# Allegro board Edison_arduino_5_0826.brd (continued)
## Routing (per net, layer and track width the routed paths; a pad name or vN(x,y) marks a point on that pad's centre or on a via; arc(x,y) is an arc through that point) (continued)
N30158362: length 3
  TOP w0.127: C42.1 98.73,32.75 R76.1 98,33 97.75,33.25 97.25,33.25 97,33.5 U3.11
N30158364: length 2.3
  TOP w0.127: U3.10 R77.1 97.23,32.75 C43.1
N30158410: length 2.4
  TOP w0.127: U3.9 96,33.5 95.75,33.25 C44.1 95.73,32.75 R78.1
N30158412: length 3.2
  TOP w0.127: R79.1 94.23,32.75 C45.1 94.25,33.25 94.5,33.5 95.25,33.5 95.5,33.75 U3.8
N30173574: length 47.5
  TOP w0.127: v1(72.39,26.04) 71.61,25.25 U34.16 ; U22.D2 102.75,38.68 v1(102.48,38.95) 102.48,38.98 103.02,39.52 104.83,39.52 R109.2
  BOTTOM w0.127: v1(102.48,38.95) 101.15,40.29 97.69,40.29 97.18,39.78 91.85,39.78 91.47,39.4 91.47,35.21 89.18,32.92 80.8,32.92 77.37,29.49 75.85,29.49 v1(72.39,26.04)
N30202561: length 3
  TOP w0.2: DS1.1 Q8.3
N30202678: length 1.8
  TOP w0.2: R86.1 37.7,39.86 DS1.2
N30202793: length 3.2
  TOP w0.2: Q9.3 49.26,28.68 49.76,29.18 DS2.1
N30202823: length 2.2
  TOP w0.2: DS2.2 48.62,29.9 R88.1
N30230113: length 1.3
  TOP w0.127: C48.2 113.59,7.62 U2.16
N30245034: length 19.5
  TOP w0.112: EU1.3 111.26,30.89 111.13,30.76 110.26,30.76 109.88,30.38 109.88,29.52 v1(109.6,29.24) ; J16.3 117.35,20.35 116.82,20.35 116.61,20.56 116.61,20.71 116.23,21.09 115.65,21.09 115.39,20.84 115.39,20.63 v1(115.11,20.35)
  BOTTOM w0.112: v1(109.6,29.24) 109.88,28.96 109.88,28.47 111.89,26.47 111.89,22.31 112.68,21.52 115.05,21.52 115.39,21.17 115.39,20.63 v1(115.11,20.35)
N30246500: length 18.7
  TOP w0.112: v1(115.91,20.35) 115.63,20.63 115.63,20.74 115.74,20.85 116.13,20.85 116.37,20.61 116.37,20.46 116.87,19.97 117.37,19.97 J16.2 ; EU1.4 111.26,30.39 111.13,30.52 110.36,30.52 110.12,30.28 110.12,29.52 v1(110.4,29.24)
  BOTTOM w0.112: v1(110.4,29.24) 110.12,28.96 110.12,28.57 112.13,26.57 112.13,22.41 112.78,21.76 115.15,21.76 115.63,21.27 115.63,20.63 v1(115.91,20.35)
N30246922: length 27.8
  TOP w0.127: 119.24,31.9 119.03,31.69 119.03,27.46 117.63,26.06 112.58,26.06 108.39,21.87 R95.2 105.82,21.86 105.82,19.97 106.2,19.59 Q10.5 ; 119.24,31.9 118.52,31.9 118,31.39 EU1.9 ; 119.24,31.9 SW1.1
N30246940: length 1.3
  TOP w0.127: R96.2 108.03,20.54 Q10.6
N30255447: length 1.5
  TOP w0.127: R97.1 117.77,32.92 SW1.C
N30255937: length 5.2
  TOP w0.127: Q11.1 116.97,36.35 117.33,36.71 R98.2 117.88,35.3 SW1.2
N30257530: length 1.7
  TOP w0.127: R100.2 27.16,49.87 Q12.6
N30257590: length 1.7
  TOP w0.127: R102.2 27.16,53.94 Q13.6
N30257808: length 2
  TOP w0.127: Q14.6 27.03,57.75 R104.2
N30258616: length 18
  TOP w0.127: R124.1 28.45,55.5 28,55.05 25.5,55.05 25.25,55.3 25.25,56.62 25.43,56.8 ; 25.43,56.8 25.17,57.05 25.17,58.19 24.54,58.83 20.47,58.83 19.84,58.19 18.96,58.19 R105.2 18.94,58.19 SW1UI5.1 ; 25.43,56.8 Q14.5
N30259742: length 12.5
  TOP w0.127: R124.2 R123.1 28.25,54.3 27.95,54.6 25.55,54.6 25.2,54.25 25.2,53.22 25.44,52.99 ; 25.44,52.99 Q13.5 ; 25.44,52.99 25.2,52.75 25.2,49.28 25.53,48.95 26.2,48.95 26.21,48.94 Q12.5
N30303973: length 25.4
  TOP w0.127: v1(97.94,28.35) 98.2,28.6 100.74,28.6 101.25,28.09 101.25,27.33 100.74,26.82 U44.2 ; v1(87.02,27.71) 87.02,27.59 88.42,26.19 88.42,22.38 88.04,22 88.04,20.35 88.17,20.22 U42.C2
  BOTTOM w0.127: v1(97.94,28.35) 96.04,28.35 95.78,28.6 87.91,28.6 v1(87.02,27.71)
N30303977: length 5.6
  TOP w0.127: v1(87.53,15.27) 87.79,15.53 U20.C1 ; U42.A1 v1(89.05,18.51)
  BOTTOM w0.127: v1(87.53,15.27) 87.78,15.27 88.55,16.03 88.55,17.93 89.05,18.44 v1(89.05,18.51)
N30305120: length 7.7
  TOP w0.127: U41.A1 106.2,36.34 v1(106.2,36.35) ; U22.C2 102.27,37.75 v1(102.26,37.75)
  BOTTOM w0.127: v1(102.26,37.75) 103.02,37.75 103.41,38.13 106.33,38.13 106.96,37.49 106.96,37.11 v1(106.2,36.35)
N30305448: length 5.5
  TOP w0.127: U40.A1 106.2,33.17 v1(106.2,33.17) ; v1(102.14,33.43) 102.21,33.5 102.75,33.5
  BOTTOM w0.127: v1(102.14,33.43) 102.64,33.43 102.9,33.68 104.67,33.68 105.18,33.17 v1(106.2,33.17)
N30330904: length 93.4
  TOP w0.3: 98.51,53.72 CR6.1 93.96,58.27 93.96,68.03 92.05,69.94 92.05,70 48.16,70 44.19,66.04 R3.2 ; CR7.1 105.65,54.47 C3.2 102.95,54.47 102.92,54.5 101.75,54.5 ; 104.81,51.82 105.03,51.61 U1.10 ; U1.13 102.98,50.35 102.68,50.66 102.68,51.8 102.67,51.81 ; 100.24,53.09 100.25,53.1 100.25,53.92 R80.2 ; U1.11 104.53,51.79 ; U1.12 104.03,51.67
N30330984: length 1.5
  TOP w0.3: C4.1 105.53,52.52 U1.9
N30331038: length 2.3
  TOP w0.3: U1.3 105.02,47.35 ; U1.1 104.02,47.46 ; U1.2 104.52,47.36
N30331073: length 2.4
  TOP w0.127: R1.2 99.12,48.98 100.46,47.65 100.46,47.47
N30331087: length 1.8
  TOP w0.127: R3.1 43.48,49.88 Q2.1
N30331321: length 15.1
  TOP w0.25: 45.43,33.96 45.43,33.62 C8.1 ; 45.43,33.96 45.42,33.97 v1(44.71,33.97) U38.12 ; 45.43,33.96 45.44,33.97 46.04,33.97 46.61,34.54 R115.2 ; U38.4 42.25,37.67 42.04,37.87 v1(41.43,37.87) 41.43,37.69 41.75,37.37 U38.5
  BOTTOM w0.25: TP84.1 v1(41.43,37.87) 42.43,36.87 43.98,36.87 44.71,36.13 v1(44.71,33.97)
N30331325: length 15
  TOP w0.127: U38.3 42.75,37.62 v1(42.8,37.68) 42.8,37.82 40.01,40.61 38.18,40.61 J13.2 ; R81.1 v1(45.43,36.59)
  BOTTOM w0.127: v1(45.43,36.59) 44.34,37.68 v1(42.8,37.68)
N30331509: length 1.4
  TOP w0.127: R4.2 41.75,33.34 U38.8
N30331521: length 2.7
  TOP w0.127: R5.1 R6.1 41.97,44.26 42.46,44.75 Q2.3
N30331562: length 7.8
  TOP w0.127: U38.1 43.75,37.86 42.62,38.99 42.62,42.41 R5.2
N30331635: length 5.7
  TOP w0.25: J2.1 42.5,32.59 42.75,32.84 U38.10
N30331680: length 8.4
  TOP w0.7: J1.1 114.28,63.53 ; J1.1 110.06,63.53 ; J1.1 112.17,61.42 ; J1.1 112.17,65.64
N30331714: length 6.2
  TOP w0.127: R1.1 99.15,49.91 R2.1 99.77,51.25 101.82,51.25 102.06,51.02 102.06,50.29 102.5,49.85 U1.14
N30332962: length 4.5
  TOP w0.127: C53.1 49.57,36.87 50.19,37.49 50.19,39.27 50.05,39.41 U45.9
N30333004: length 2.9
  TOP w0.127: R112.2 R111.1 47.27,38 47.66,38.39 U45.5
N30333010: length 6.2
  TOP w0.3: U45.1 46.12,40.91 46,40.79 46,40.41 ; U45.3 46.01,39.91 46,39.91 ; 46,40.41 46,39.91 ; 46,40.41 46,40.41 U45.2 ; 46,39.91 46,39.52 45.62,39.14 L2.1
N30351958: length 15.6
  TOP w0.127: R97.2 117.75,33.44 v1(117.09,34.1) CR9.1 ; v1(113.18,23.31) 113.18,23.31 CR8.1
  BOTTOM w0.127: v1(113.18,23.31) 113.18,25.2 117.09,29.11 v1(117.09,34.1)
N30369476: length 18.1
  TOP w0.127: DS3.2 41.69,42.4 v1(41.7,42.41) ; R114.1 53.66,40.58 v1(53.07,41.18)
  BOTTOM w0.127: v1(53.07,41.18) 53.07,42.62 50.79,44.9 47.07,44.9 46.79,45.17 45.39,45.17 45.05,44.83 42.42,44.83 41.2,43.6 41.2,42.92 v1(41.7,42.41)
N30369490: length 4.2
  TOP w0.127: U38.2 43.25,37.99 41.69,39.55 DS3.1

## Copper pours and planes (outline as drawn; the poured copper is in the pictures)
4.38V on TOP: 44.85,43.44 44.85,42.16 45.51,41.5 45.51,41.14 45.01,40.64 43.45,40.64 43.06,41.03 43.06,43.37 43.36,43.67 44.61,43.67
4.38V on BOTTOM: 42.4,39.2 43.41,38.19 44.8,38.19 45.75,37.24 45.75,32.67 46,32.41 47.4,32.41 47.78,32.79 47.78,34.19 50.83,37.24 50.83,43.21 50.19,43.84 43.44,43.84 42.4,42.8
5V on TOP: 48.41,34.57 50.57,36.73 50.57,41.3 49.81,41.3 49.81,42.19 49.05,42.19 49.05,42.95 48.8,43.21 48.29,43.21 48.03,43.46 48.03,44.48 47.5,45.01 47.5,46.48 46.48,47.5 46.48,64.9 49.91,68.33 89.41,68.33 91.34,66.4 91.34,59.34 97.54,53.14 97.54,51.69 98.25,50.98 98.25,49.36 99.47,48.13 99.47,46.74 97.54,46.74 97.54,43.36 97.69,43.21 103.78,43.21 104.42,43.84 105.56,43.84 105.56,42.19 105.31,41.94 88.31,41.94 88.2,42.05 88.2,44.51 85.98,46.74 84.11,46.74 83.56,47.29 83.56,49.71 84.02,50.18 88.5,50.18 91.33,47.35 93.75,47.35 94,47.6 94,49.85 93.7,50.15 91.6,50.15 88.6,53.15 86.39,53.15 86.39,54.12 84.23,56.28 81.64,56.28 80.9,57.02 80.9,61.49 81.2,61.8 82.37,61.8 82.83,62.26 82.83,63.12 52.58,63.12 49.4,59.94 49.4,51.3 50.91,49.78 50.91,43.95 52.73,42.14 52.73,33.43 52.96,33.27 54.86,33.27 55.24,32.89 55.24,31.24 54.99,30.99 50.22,30.99 48.41,32.79
5V on TOP: 91.21,38.64 88.93,38.64 88.42,39.14 88.42,40.67 90.45,40.67 91.21,39.91
5V on BOTTOM: 87.7,45.55 87.7,39.48 88.67,38.51 90.58,38.51 91.09,39.02 91.09,40.16 90.7,40.54 90.7,44.35 89.05,46 88.15,46
5V on BOTTOM: 48.16,34.06 48.16,33.3 48.8,32.67 49.68,32.67 50.45,33.43 50.45,34.06 50.19,34.32 48.41,34.32
5V on BOTTOM: 103.84,43.67 103.84,41.19 104.7,40.33 108.91,40.33 111.39,37.85 111.39,37.07 111.12,36.8 111.12,33.31 111.54,32.89 112.64,32.89 112.93,33.18 112.93,38.1 107.01,44.02 104.19,44.02
GND on TOP (solid shape): 101.18,49.77 101.46,49.49 103.35,49.49 103.42,49.42 103.42,49.19 102.95,49.19 102.95,49.01 103.42,49.01 103.42,48.82 103.35,48.75 102.98,48.75 102.54,48.31 100.66,48.31 100.4,48.57 100.4,50.29 100.56,50.45 101.18,50.45
GND on TOP: 24.16,57.43 22.89,57.43 22.63,57.18 21.49,57.18 21.36,57.3 21.36,58.19 21.49,58.32 24.16,58.32 24.28,58.19 24.28,57.56
GND on TOP: 15.53,11.54 15.53,10.88 16.56,9.85 16.93,9.85 17.13,10.04 17.13,10.44 17.41,10.73 17.41,11.43 17.17,11.67 15.66,11.67
GND on TOP: 45.57,42.97 45.73,42.97 46.56,42.15 47.83,42.15 47.99,42.31 47.99,42.61 47.25,43.35 47.25,44.88 46.14,45.98 45.38,45.98 45.17,45.77 45.17,44.17 45.57,43.77
GND on TOP: 24.16,49.56 22.89,49.56 22.63,49.3 21.49,49.3 21.36,49.43 21.36,50.32 21.49,50.45 24.16,50.45 24.28,50.32 24.28,49.68
GND on TOP: 19.2,11.61 19.43,11.61 19.43,10.69 19.46,10.67 19.58,10.67 19.61,10.69 19.61,11.61 19.81,11.61 19.81,10.69 19.84,10.67 19.99,10.67 20.02,10.69 20.02,11.61 20.22,11.61 20.22,10.69 20.24,10.67 20.4,10.67 20.42,10.69 20.42,11.61 20.62,11.61 20.62,10.08 20.5,9.96 20.09,9.96 19.66,9.53 19.66,6.76 19.28,6.38 16.56,6.38 16.03,6.91 16.03,7.77 16.74,8.48 17.09,8.48 19.2,10.59
GND on TOP: 102.62,63.63 102.62,59.18 104.14,57.66 107.82,57.66 108.74,58.57 108.74,64.67 103.66,64.67
GND on TOP: 24.16,53.62 22.89,53.62 22.63,53.37 21.49,53.37 21.36,53.49 21.36,54.38 21.49,54.51 24.16,54.51 24.28,54.38 24.28,53.75
GND on BOTTOM: 101.09,63.75 101.09,56.77 102.62,55.25 106.3,55.25 109.09,58.04 109.09,65.28 108.84,65.53 102.87,65.53
GND on GND: 121.33,0.89 0.93,0.89 0.93,71.08 121.33,71.08 ; 1 cut-out
GND on PWR_GND: 121.33,0.89 0.93,0.89 0.93,71.08 121.33,71.08 ; 1 cut-out
VBUS on TOP: 16.28,21.11 16.28,20.09 19.2,17.17 20.22,17.17 20.6,16.79 21.24,16.79 21.36,16.92 21.36,17.93 17.93,21.36 16.54,21.36
VBUS on TOP: 102.01,19.59 102.01,16.66 103.79,14.89 115.22,14.89 115.6,15.27 115.6,16.79 114.71,17.68 103.66,17.68 103.53,17.81 103.53,19.84 102.26,19.84
VBUS on PWR_GND: 116.2,37.77 116.2,16.89 116.46,16.64 121.28,16.64 121.28,0.89 15.02,0.89 15.01,20.14 16.08,21.21 17.5,21.21 18.35,20.36 18.35,3.17 18.73,2.79 107.44,2.79 113.44,8.79 113.44,22.38 114.33,23.27 114.33,34.83 107.72,41.43 107.72,41.94 108.1,42.32 111.66,42.32
VBUS_IN on TOP: 108.5,20.26 108.5,19.87 108.28,19.65 107.92,19.65 107.61,19.35 107.61,18.99 107.49,18.88 106.77,18.88 106.66,18.77 106.66,18.44 106.73,18.38 116.56,18.38 116.67,18.49 116.67,19.28 116.45,19.5 111.43,19.5 110.61,20.33 108.57,20.33
VBUS_OUT on PWR_GND: 111.53,44.86 106.2,44.86 105.82,44.48 105.82,40.41 111.64,34.59 111.64,24.48 105.6,18.44 103.79,18.44 97.31,11.97 42.83,11.97 37.75,17.05 37.75,26.82 36.48,28.09 25.94,28.09 25.55,28.48 25.55,37.11 24.79,37.87 23.9,37.87 23.14,37.11 23.14,28.35 25.81,25.68 34.44,25.68 35.46,24.67 35.46,16.66 41.3,10.82 41.3,5.74 42.19,4.85 95.53,4.85 114.07,23.4 114.07,34.7 107.34,41.43 107.34,42.32 107.72,42.7 111.53,42.7
VIN on TOP (solid shape): 100.08,59.82 100.08,56.39 98.04,56.39 98.04,57.44 97.35,58.13 95.81,58.13 95.52,58.42 95.52,61.4 95.71,61.59 98.3,61.59
VIN on TOP: 95.71,61.59 98.3,61.59 100.08,59.82 100.08,56.39 98.04,56.39 98.04,57.44 97.35,58.13 95.81,58.13 95.52,58.42 95.52,61.4
VIN on PWR_GND: 73.03,61.59 73.03,57.28 73.66,56.64 96.52,56.64 96.52,61.59
(no net) on TOP: 100.66,48.31 102.54,48.31 102.98,48.75 103.35,48.75 103.42,48.82 103.42,49.42 103.35,49.49 101.46,49.49 101.18,49.77 101.18,50.45 100.56,50.45 100.4,50.29 100.4,48.57
(no net) on TOP: 102.21,46.06 102.5,45.77 102.5,44.66 101.34,44.66 100.27,43.59 98.07,43.59 97.94,43.72 97.94,44.35 99.21,44.35 100.25,45.38 100.25,47.39 100.52,47.67 101.36,47.67 102.21,46.82
(no net) on TOP: 98.2,53.84 98.2,52.07 98.47,51.8 102.87,51.8 103.02,51.64 104.91,51.64 105.08,51.82 105.08,51.9 104.78,52.21 104.78,54.13 105.85,54.13 105.92,54.2 105.92,54.78 105.82,54.89 103.79,54.89 103.61,54.71 103.61,54.11 103.5,54 102.76,54 102.62,54.14 102.62,54.36 102.18,54.8 101.55,54.8 101.25,54.5 101.25,53.55 101,53.3 99.68,53.3 98.99,53.98 98.34,53.98
(no net) on TOP: 105.2,48.35 104.89,48.35 104.89,47.69 104.87,47.67 104.71,47.67 104.69,47.69 104.69,48.35 104.38,48.35 104.38,47.69 104.36,47.67 104.21,47.67 104.18,47.69 104.18,48.35 103.88,48.35 103.88,46.8 103.04,45.97 103.04,44.67 105.2,44.67
(no net) on TOP: 95.71,61.59 98.3,61.59 100.08,59.82 100.08,56.39 98.04,56.39 98.04,57.44 97.35,58.13 95.81,58.13 95.52,58.42 95.52,61.4
V_1P80 on PWR_GND: 12.73,64.54 70.33,64.54 72.64,62.23 72.64,57.15 73.53,56.26 98.55,56.26 99.06,55.75 99.06,46.48 103.28,42.26 103.28,40.16 105.69,40.16 111.37,34.48 111.37,24.62 105.58,18.82 103.53,18.82 97.16,12.45 42.8,12.45 38.1,17.15 38.1,26.92 36.58,28.45 26.29,28.45 26.04,28.7 26.04,37.08 24.64,38.48 17.78,38.48 17.14,39.12 17.14,41.02 11.68,41.02 10.92,41.78 10.92,62.74 ; 1 cut-out
V_1P80_IO on TOP: 21.36,52.99 21.49,53.11 23.01,53.11 23.14,53.24 24.16,53.24 24.28,53.11 24.28,51.72 24.16,51.59 21.49,51.59 21.36,51.72
V_1P80_IO on BOTTOM: 23.39,52.61 23.39,51.34 22.76,50.7 19.84,50.7 18.95,51.59 18.95,61.11 22.51,64.67 47.14,64.67 50.32,61.5 54.64,61.5 55.91,60.23 55.91,59.34 56.41,58.83 62,58.83 64.42,56.42 64.42,50.57 64.54,50.45 65.3,50.45 65.56,50.19 65.56,49.56 65.05,49.05 62,49.05 58.32,52.73 58.32,54.89 54,59.21 43.59,59.21 40.41,62.38 22.63,62.38 20.86,60.61 20.86,55.15
V_1P80_IO on BOTTOM: 66.19,28.09 66.19,27.59 67.46,26.32 69.11,26.32 69.62,25.81 70.64,25.81 70.77,25.94 70.77,26.7 70.39,27.08 69.11,27.08 67.97,28.22 66.32,28.22
V_1P80_IO on PWR_GND: 70.89,28.6 70.89,25.94 70.51,25.55 58.7,25.55 54.89,29.36 51.21,29.36 50.57,30 50.57,37.75 47.14,41.18 22.76,41.18 18.95,44.98 18.95,50.95 21.11,53.11 23.14,53.11 23.65,52.61 23.65,50.06 22.89,49.3 20.98,49.3 20.35,48.67 20.35,46.64 22.89,44.1 49.3,44.1 56.67,36.73 56.67,30.51 58.57,28.6
V_3P30 on BOTTOM: 12.07,64.01 19.18,71.12 96.31,71.12 100.08,67.35 100.08,55.93 101.78,54.23 113.28,54.23 116.99,50.52 116.99,32.16 116.61,31.78 115.47,31.78 113.31,33.94 113.31,38.25 106.88,44.69 95.83,44.69 93.78,46.74 84.64,46.74 79.22,52.15 79.22,53.37 75.45,57.14 75.45,62.55 70.81,67.18 22.35,67.18 21.97,66.8 21.97,65.91 18.41,62.36 18.41,38.61 17.91,38.1 12.57,38.1 12.07,38.61
V_SHIELD on TOP: 79.41,49.06 79.41,46.5 77.63,46.5 76.63,47.5 75.03,47.5 74.93,47.39 74.93,46.38 79.97,41.34 80.95,41.34 81.1,41.49 81.1,43.01 80.85,43.26 80.38,43.26 80.22,43.41 80.22,44.02 80.63,44.43 82.18,44.43 82.42,44.66 82.42,49.13 83.74,50.46 85.72,50.46 85.72,50.45 88.7,50.45 91.5,47.65 93.5,47.65 93.6,47.75 93.6,49.7 93.45,49.85 91.4,49.85 88.45,52.8 85.75,52.8 85.75,52.81 83.16,52.81
V_SHIELD on TOP: 54.46,40.2 54.46,39.64 55.68,39.64 57.77,37.55 57.77,34.19 58.63,33.33 60.74,33.33 61.03,33.62 61.03,35.72 55.7,41.04 55.05,41.04 54.93,40.93 54.93,40.93 54.93,40.28 54.93,40.27 54.86,40.2
V_SHIELD on BOTTOM: 88.95,60.19 88.95,55.91 85.04,52 84.7,52 84.29,51.59 84.29,51.05 84.77,50.56 85.46,50.56 90.68,55.78 90.68,60.27 90.16,60.79 89.54,60.79
V_SHIELD on BOTTOM: 75.31,47.88 79.63,47.88 82.42,45.09 82.42,36.45 77.47,31.5 74.8,31.5 74.55,31.75 74.55,32.39 76.2,34.04 76.2,43.94 74.96,45.19 74.96,47.53
V_SHIELD on GND: 62.87,40.77 74.28,40.77 74.84,41.33 77.92,41.33 78.23,41.02 78.23,38.86 77.58,38.21 75.54,38.21 74.89,38.86 62.87,38.86
V_SHIELD on PWR_GND: 64.29,40.79 64.29,40.54 64.03,40.29 61.75,40.29 59.97,42.06 59.97,53.49 59.21,54.26 56.54,54.26 56.16,53.88 56.16,48.41 55.15,47.4 28.6,47.4 27.71,48.29 27.71,49.56 27.97,49.81 46,49.81 50.45,54.26 50.45,55.65 52.86,58.07 56.54,58.07 61.37,53.24 61.37,42.19 62.51,42.19 63.4,41.3 63.78,41.3
V_SHIELD on PWR_GND: 59.94,36.45 79.3,36.45 85.35,30.4 81.29,30.4 79.28,32.41 59.59,32.41 59.59,36.09
V_SHIELD_SW on PWR_GND: outline of 121 points within 56.77,16.76 92.48,46.99
V_SHLD_IO on TOP: 21.36,48.92 21.49,49.05 22.89,49.05 23.01,49.18 24.16,49.18 24.28,49.05 24.28,47.65 24.16,47.53 21.49,47.53 21.36,47.65
V_SHLD_IO on PWR_GND: 20.6,48.41 20.6,46.76 23.01,44.35 49.43,44.35 57.05,36.73 57.05,30.63 58.83,28.86 78.77,28.86 80.8,26.82 82.58,26.82 82.6,26.85 85,26.85 85.35,27.2 85.35,29.5 85.04,29.82 81.62,29.82 79.28,32.16 59.34,32.16 59.34,38.13 56.16,41.3 56.16,46.64 55.65,47.14 25.17,47.14 23.27,49.05 21.24,49.05
V_SYS on BOTTOM: 21.36,45.11 23.9,47.65 23.9,54.38 23.27,55.02 21.87,55.02 21.36,55.53 21.36,60.61 22.35,61.59 34.29,61.59 38.23,57.66 38.23,51.82 37.72,51.31 31.75,51.31 31.12,50.67 31.12,42.09 32.79,40.41 35.97,40.41 38.63,37.75 38.63,34.7 40.03,33.3 44.86,33.3 46,32.16 47.14,32.16 47.27,32.03 47.27,31.27 46.48,30.48 31.62,30.48 30.99,31.12 21.36,31.12
V_SYSTEM on TOP: 23.05,56.96 23.14,57.05 24.16,57.05 24.28,56.92 24.28,55.53 24.16,55.4 21.5,55.4 20.3,55.4 19.85,54.95 19.85,48.45 10.65,39.25 10.65,38.45 10.5,38.3 6.4,38.3 6.1,38.6 6.1,40.45 6.48,40.83 9.03,40.83 17.7,49.5 17.7,55.2 19.46,56.96
N30057609 on TOP: 94.59,37.36 91.74,37.36 91.74,38.99 94.59,38.99
N30057609 on BOTTOM: 92.46,39.24 97.16,39.24 99.82,36.58 99.82,35.05 99.44,34.67 93.98,34.67 92.2,36.45 92.2,38.99
N30126876 on TOP: 18.62,14.99 15.36,14.99 15.15,15.19 12.75,15.19 10.79,17.15 10.79,34.29 10.03,35.05 6.6,35.05 6.1,35.56 6.1,37.97 6.22,38.1 12.19,38.1 12.32,37.97 12.32,20.83 17.6,15.54 18.34,15.54 18.62,15.27
N30126894 on TOP: 19.43,14 19.2,14 19.2,14.91 19.18,14.94 19.05,14.94 19.02,14.91 19.02,14 18.82,14 18.82,15.34 18.41,15.75 17.78,15.75 12.57,20.96 12.57,37.97 12.7,38.1 16.76,38.1 17.14,37.72 17.14,36.07 15.88,34.8 15.88,20.07 18.67,17.27 18.67,16.41 19.43,15.65
N30126899 on BOTTOM: 20.19,15.49 19.44,15.49 18.56,16.38 18.56,16.91 18.79,17.14 19.81,17.14 20.57,17.91 20.57,20.7 20.45,20.83 19.68,20.83 19.56,20.7 19.56,19.81 19.18,19.43 18.52,19.43 17.58,18.49 17.58,14.74 18.1,14.22 20.19,14.22 20.45,14.48 20.45,15.24
N30126899 on PWR_GND: 21.62,20.35 21.34,20.07 20.19,20.07 19.94,20.32 19.94,31.04 18.57,32.41 18.57,37.62 19.05,38.1 21.01,38.1 21.62,37.49
N30330904 on TOP (solid shape): 105.92,54.78 105.92,54.2 105.85,54.13 104.78,54.13 104.78,52.21 105.08,51.9 105.08,51.82 104.91,51.64 103.02,51.64 102.87,51.8 98.47,51.8 98.2,52.07 98.2,53.84 98.34,53.98 98.99,53.98 99.68,53.3 101,53.3 101.25,53.55 101.25,54.5 101.55,54.8 102.18,54.8 102.62,54.36 102.62,54.14 102.76,54 103.5,54 103.61,54.11 103.61,54.71 103.79,54.89 105.82,54.89
N30331038 on TOP (solid shape): 104.18,48.13 104.18,47.69 104.21,47.67 104.36,47.67 104.38,47.69 104.38,48.35 104.68,48.35 104.68,47.77 104.69,47.77 104.69,47.69 104.71,47.67 104.87,47.67 104.89,47.69 104.89,48.35 105.18,48.35 105.18,47.77 105.2,47.77 105.2,44.67 103.04,44.67 103.04,45.97 103.88,46.8 103.88,48.35 104.18,48.35
N30331073 on TOP (solid shape): 100.63,47.67 101.36,47.67 102.21,46.82 102.21,46.06 102.5,45.77 102.5,44.66 101.34,44.66 100.27,43.59 98.07,43.59 97.94,43.72 97.94,44.35 99.21,44.35 100.25,45.38 100.25,47.39 100.52,47.67 100.63,47.67
N30331680 on TOP: 115.7,59.56 109.5,53.37 108.74,53.37 108.33,53.78 108.33,56.52 109.5,57.69 109.5,65.31 110.14,65.94 113.82,65.94 115.7,64.06

Small or netless copper shapes (teardrops, artwork), in the pictures only: 3 on TOP

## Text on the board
BOTTOM: 4 | H40482-005
User.Comments: UNLESS OTHERWISE SPECIFIED: | 1. DIMENSIONS ARE IN INCHES | 2. BREAK ALL SHARP EDGES | 3. DO NOT SCALE DRAWING | 4. TOLERANCES | ANGLES +/- | DRN BY | CHK BY | ENGR | APVD | SIGNATURE | DATE | SCALE | TITLE | SIZE | DCLC | CLASS CODE | DOCUMENT NUMBER | SHEET | OF | REV
TOP: 1
Ref Des/Silkscreen Top: ANALOG IN | DIGITAL(PWM~) | RM | FW | RESET | PWR | SHLD RST | - | POWER | BATT | + | PWM | RX | 0 | A5 | TX | 1 | A4 | 2 | A3 | ~3 | A2 | 4 | A1 | ~5 | A0 | ~6 | 7 | VIN | GND | 8 | ~9 | 5V | ~10 | 3.3V | ~11 | 12 | IOREF | 13 | AREF | SDA | SCL
GND: 2
PWR_GND: 3
DIMENSION: -A- | -B-
PAGE_OUTLINE: THIS DRAWING CONTAINS INFORMATION | WHICH IS THE PROPRIETARY PROPERTY | OF INTEL CORPORATION. THIS DRAWING | IS RECEIVED IN CONFIDENCE AND ITS | CONTENTS MAY NOT BE DISCLOSED WITH- | OUT THE PRIOR WRITTEN CONSENT OF | INTEL CORPORATION. | D | C | B | A | 8 | 7 | 6 | 5 | 4 | 3 | 2 | 1
DISPLAY_TOP: PROCESS FLOW | WAVE & SMT
User.6: 0 | # | A | B | 1 | 2 | 3 | 4
User.7: K | L | M | 4 | 3 | 2 | 1 | 0
User.24: DETAILS "A" | 4 PLACES
User.31: SHEET | TITLE | SCALE 1:1 | LAYER | OF | DOCUMENT NUMBER | REV | H40482-005 | 01 | INTEL | MASTER | EDISON ARDUINO | 08/11/14
User.32: 4 | DEV,PB,
User.33: LAYER 4 (SECONDARY SIDE) | 4
User.34: LAYER 3 (PWR/GND PLANE) | 3
User.35: LAYER 2 (GND PLANE) | 2
User.36: LAYER 4 (SIGNAL/POWER) | 4
User.37: LAYER 5 (GND PLANE) | 5
User.38: LAYER 1 (PRIMARY SIDE) | 1
User.39: SECONDARY SIDE
User.40: jeirvin | 04/10/14 | W.GILLMER | 08/11/14 | REV | DESCRIPTION | DFT | REVISIONS | DATE | CHK | APVD | 01 | INITIAL RELEASE | 6   MARK SERIAL NUMBER PER INTEL MARKING STANDARD | 164997 APPROXIMATELY WHERE SHOWN, PRIMARY SIDE. | 7   ONLY SITES OTHER THAN USA & PUERTO RICO SHALL | MARK "MADE IN (COUNTRY OF ORIGIN)" PER INTEL | MARKING STANDARD 164997 APPROXIMATELY WHERE | SHOWN, PRIMARY SIDE. | 8.  SOCKET REFERENCE DESIGNATORS ON ENGINEERING | PARTS LIST ARE THE COMPONENT REFERENCE | DESIGNATORS PREFIXED WITH "X". | 9   MARK PRODUCT CODE PER INTEL MARKING STANDARD | SELECT APPROPRIATE PRODUCT CODE PREFIX PER | SITE POLICY. | 10. PRODUCT CODE IS PER ENGINEERING PARTS LIST. | NOTES: UNLESS OTHERWISE SPECIFIED: | 1.  ITEM IDENIFICAITON NUMBER IS PARENT LINE ITEM | NUMBER ON ENGINEERING PARTS LIST. | 2.  THIS DOCUMENT ALSO EXISTS ON ELECTRONIC MEDIA. | 3.  WORKMANSHIP PER INTEL 99-0007-001. | 4   MARK "PBA" AND ITEM IDENTIFICATION NUMBER PER | INTEL MARKING STANDARD 164997 APPROXIMATELY | WHERE SHOWN, PRIMARY SIDE. | 5   MARK ASSEMBLY VENDOR IDENTIFICATION PER INTEL | SHOWN, SECONDARY SIDE. | 1:1 | H40482-005 | 1 | PBA, EDISON ARDUINO | PRIMARY SIDE
User.41: LAYER(S) | 1 AND 6 | FINISHED TRACE | WIDTH (MILS) | 4.4 | IMPEDANCE CHART | JEIRVIN | (EDGE TO EDGE) | TRACE SPACING | 5.0 | 04/10/2014 | REQUIRED IMPEDANCE | 90 OHMS | 08/11/14 | TOLERANCE | +/- 10% | REV | INITIAL RELEASE | DESCRIPTION | W.GILLMER | DFT | REVISIONS | DATE | CHK | APVD | 8 | 24 | 9 | NOTES: UNLESS OTHERWISE SPECIFIED: | 18 V-GROOVE MAY BE LOCATED IN AN AREA +/- 0.010" ON EITHER SIDE OF V-GROOVE CENTERLINE. | 19 V-GROOVE SEPARATION DENOTED BY LINE. | 20 SOLDERMASK MUST NOT EXCEED .001 THICKNESS FROM TOP OF COPPER FEATURE TO TOP OF SOLDERMASK | 21 NO EXPOSED METAL ALLOWED ON TOP SIDE VIA PADS WHERE SHOWN | IN THIS AREA ON TOP SIDE ONLY | 22 NO SOLDERMASK ALLOWED ON SMT PADS | 23 SOLDERMASK MAY ENCROACH ON VIA'S IN ORDER TO CREATE A SOLDERMASK WEB BETWEEN VIA AND PAD. | 17.DELIVERY REQUIREMENTS: | 24. THIEVING ALLOWED ON OUTRIGGERS (BREAKAWAY SECTIONS). | 13.FINISH: ENIG | 14.MATERIAL: 370HR OR EQUIVALENT | 15.SOLDERMASK COLOR: BLUE. SILKSCREEN COLOR: WHITE | 10.SMT LAND PATTERNS THAT HAVE A FINISHED PAD WIDTH RANGING FROM | .012 TO .015 MUST USE THE FOLLOWING TOLERANCE, +.002 -.0005. | PB VENDOR TO ADJUST ARTWORK TO COMPENSATE FOR ETCH PROCESS | 11.THIS BOARD REQUIRES VIA CAPPING ON THE SECONDARY SIDE. ALL | VIA CAPPING SHALL FILL 50 TO 90% OF THE HOLE. COVERAGE FOR | ALL VIA IN PAD (VIP) DEVICES SHALL BE 100% PER INTEL | SPECIFICATION 454979. | 12.THESE PADS ARE TO BE COVERED BY SOLDERMASK ON THE PRIMARY AND | SECONDARY SIDES PER THE ARTWORK EXCEPT AS NOTED IN NOTE 16. | 16.ALL PADS MUST NOT BE COVERED BY SOLDERMASK ON THE SECONDARY | 7. COMPARE SUPPLIED IPC-D-356 NETLIST TO SUPPLIED GERBER DATA | PRIOR TO FABRICATION. | SIDE PER THE ARTWORK - SEE FAB SHEETS 2 AND 3 FOR EXCLUSIONS. | 6. DIMENSIONING AND TOLERANCING PER ANSI Y14.5M. | 25. TOLERANCE OF BOARD OUTLINE IS +/-0.127MM (5MILS). | 4  THE CENTER OF THIS HOLE ESTABLISH DATUM -A-. | 5  DATUM -B- IS ESTABLISHED PERPENDICULAR TO DATUM -A- THROUGH | THE CENTER OF THIS HOLE. | 8  THESE HOLES MAY BE PLATED SHUT. | NOTE: THE IMPEDANCE CHARTS WILL REFLECT ALL POSSIBLE | IMPEDANCE VALUES WHICH MAY BE REQUIRED IN THE DESIGN. NOT | ALL VALUES WILL BE PRESENT ON EACH LAYER. | 9  CONTROLLED IMPEDANCE: SEE LAYER STACK AND IMPEDANCE CHART. | 3. FABRICATE PER INTEL SPECIFICATION A84501. | 2. THIS DRAWING ALSO EXISTS ON ELECTRONIC MEDIA. | 1. ITEM IDENTIFICATION NUMBER IS PARENT LINE ITEM NUMBER ON | A. TWO BARE BOARDS (SOLDER SAMPLE) AND CROSS-SECTION SHALL BE | B. A TDR REPORT, ONE PER PANEL SHALL ACCOMPANY THE MATERIAL | ENGINEERING PARTS LIST. | INCLUDED WITH EACH BOARD LOT. | SHIPMENT. | 1:1 | 1 | 01 | PB, EDISON ARDUINO | H40482-005 | D
User.42: - | SILKSCREEN(SECONDARY) | 1 | DEV,PBA,SSB,
User.43: - | SILKSCREEN (PRIMARY) | 1 | DEV,PB, SST,
User.44: - | SOLDER MASK (SECONDARY) | 1 | DEV,PB,SMB,
User.45: D | C | B | A | 2 | 1 | 3 PLCS/Side | 20 PLCS | Q1L2 | R1M6 | LINK | Q1L1 | C2L9 | SPEED | C2L12 | L2M1 | C2L11 | C2L4 | C2L6 | C3M11 | C3M4 | C3L12 | C3L23 | C3L16 | C3L7 | C3L3 | CR3M1 | C4M6 | R1M10 | R1M9 | R1M8 | R1M7 | R1M2 | C1L2 | C1L1 | R1L11 | R1M12 | C1M7 | C1L3 | U1L3 | R1M4 | C1M5 | R1M5 | C1M13 | C1M14 | U1L1 | U1L2 | R1M3 | R5 | R8 | C1M1 | C1M2 | 14 | 13 | R1L10 | U1L4 | C1M6 | 7 | R6 | R3M22 | R1L7 | R2L20 | R1L3 | C2L7 | 6 | R2L1 | 12 | R2M4 | 52 | 16 | 15 | 17 | C2M6 | R2M2 | 51 | R2L16 | R2L17 | R2L12 | R2L7 | R2L8 | R2L6 | R2L4 | R2M11 | R2L5 | R2L13 | C2M10 | C2M8 | U2M1 | C2L5 | R2L2 | R3M2 | C2L1 | C2L13 | C3L13 | R2L21 | C2M9 | R3M13 | C2M2 | R3M8 | C3L5 | R3M1 | R3M5 | C3M6 | R3L11 | C3M5 | Y3L1 | C3M12 | R3M11 | R3L13 | R3L2 | C3M8 | R3L12 | R3L6 | R3L9 | R3L8 | C3L6 | FB3M1 | R3L7 | C3M3 | R3M15 | R3M20 | C3L1 | R1B1 | R4M2 | C4M1 | C4L1 | R4L11 | C4M5 | C3L19 | C4M4 | C6 | C9 | R1B2 | C3L15 | C3M1 | C3L11 | C7 | C8 | C3L22 | C3L21 | R2M13 | R2M10 | R2M9 | R2M12 | R2M7 | R2M8 | R2M14 | C3L28 | C3L14 | FB1M1 | C2L8 | C2M7 | C3M9 | C3L2 | C3L4 | R1M1 | C1M8 | C1M9 | C1M10 | C1M4 | R1L1 | R1M11 | R1L5 | C1M11 | C1M12 | R2M15 | C2L2 | R2L15 | R2M1 | R1L2 | R2M6 | R2M3 | R2L19 | R2L14 | C2M5 | C2L14 | C2L3 | C2L10 | R2L3 | C2M4 | U2L1 | R2L11 | R2L10 | R2L18 | R2L9 | R3M14 | R2M5 | R3M10 | C3L8 | C3L9 | C3L10 | L3M1 | R3L3 | R3M9 | R3L14 | R3L10 | R3M6 | L3M2 | R3M16 | R3M7 | C3M10 | R3M17 | R3M18 | R3M19 | R3L1 | R4L1 | R4L9 | C3L27 | C4M3 | R4L10 | R4L2 | C3L25 | C4M2 | C4L2 | C4L3 | R4L12 | R4M1 | R4L19 | R4L13 | C3L24 | C3L18 | R4L14 | R4L15 | C3L20 | R4L21 | R4L16 | C3L17 | R4L20 | C3M2 | R3L4 | R4L3 | R4L17 | R4M12 | FB3L1 | R4L4 | C3L30 | R4L18 | R4M11 | R4L23 | R4M10 | R4L22 | R4M9 | R4L5 | R4M8 | R4L6 | R4L7 | R4M7 | R4L8 | R15 | C3L29 | C3L26 | LATCH | 5 | J2L1 | C1M3 | 8 | C3M13 | R3M21 | Scale 4X | 1.56718MM | .06731 | PLANE | SIGNAL | 1.27 | LAYER STACKING | SCALE: NONE | LAYER 4 (0.5 OZ) | LAYER 2 (1.0 OZ) | LAYER 3 (1.0 OZ) | LAYER 1 (0.5 OZ) | TYP 2.54 | 1.00 Copper/metal | TYP 5.54 | 3.00 Soldermask opening | 169.187 | 5.000 | 8.000 | 246.990 | (x4)R3.00 | 2. VIA PLUGS NEED TO BE ADDED TO THE THERMAL PADS AREAS AS SHOWN. | 1. TOP VIA PLUG LAYER: ALL VIAS TO BE PLUGGED FROM TOP SIDE WITH SOLDER MASK EXCLUDING VIAS DEFINED IN BOTTOM VIA PLUG LAYER. | 1. | 1. THE VIAS WITHIN THE AREAS BELOW SHOULD BE PLUGGED FROM BOTTOM SIDE | 2. THE VIAS WITHIN THE AREAS BELOW SHOULD BE UN-PLUGGED FROM TOP SIDE | 25MHZ | PCIE | 2. | MAC ADDRESS | LB3 | TMS | TCK | TD0 | TDI | TRST | LB6V1 | 1) NPTH locational tolerance = +/-0.05mm from datum | 2) Copper feature to NPTH hole tolerance = +/- 0.10mm. | 3) Panel outline tolerance = +/- 0.15mm. | 4) Primary side of PCB is shown. | 5) PCB fabricator may add dummy copper on the breakaway, but not | on the break-out tabs. | 6) Copper keep out area. | 7) Unit: mm [inch]. | Fiducial Detail | Break-out Tab Detail | - | (NPTH X4) DIA 3.050 +/-0.050 | SOLDER PASTE (PRIMARY) | SOLDER MASK (PRIMARY) | SOLDER PASTE (SECONDARY) | LB1 | DEV,PB,SPB, | DEV,PB,SPT, | DEV,PB,SMT, | FIGURE | SIZE | 0.2032 | 0.254 | 0.3556 | 0.9652 | 1.016 | 1.2446 | 2.0 | 2.3114 | 2.667 | 3.175 | 3.18 | 0.8128 | 1.9304x0.7112 | 0.1016 | DRILL CHART: TOP to BOTTOM | ALL UNITS ARE IN MILLIMETERS | DRILL CHART: TOP to GND | TOLERANCE | +0.0/-0.2032 | +0.0/-0.254 | +0.1016/-0.2032 | +0.0762/-0.0762 | +0.0/-0.0 | +0.127/-0.127 | +0.08/-0.08 | +0.0254/-0.1016 | PLATED | NON-PLATED | QTY | 643 | 4 | 18 | 41 | 11 | Top Side View | PANELIZATION DETAIL
